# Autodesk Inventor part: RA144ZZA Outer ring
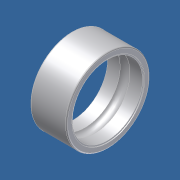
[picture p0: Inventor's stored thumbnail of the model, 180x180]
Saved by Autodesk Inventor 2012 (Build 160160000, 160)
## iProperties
Category: PARTsolutions
Created: 2011-07
Part Number: RA144ZZA Outer ring
Catalog Web Link: www.cadenas.de
Description: Six types or - Inch system sizes
Document SubType Name: Modeling
Designer: PARTsolutions
Density: 1 g/cm^3
Material: Par défaut
NB: RA144ZZA Outer ring
NN: Six types or
NT: Inch system sizes
NBSYN: RA144ZZA Outer ring
LINA: RA144ZZA Outer ring
SD: 3.175
D: 6.350
B: 2.380
B1: 2.779
D1: 7.52
D2: 7.52
C1: 0.58
C2: 0.79
R: 0.08
ORDER: RA144ZZA
CR: 284
COR: 96
CRF: 29
CORF: 10
LSG: 59000
LSO: 70000
MASS: 0.27
ORDER1: R144
WSS: RA144ZA
WDS: RA144ZZA
UTWF: FLR144
FORSS: FLRA144ZA
FORDS: FLRA144ZZA
DA1: 3.9
DA2: 4
DA: 5.5
RAS: 0.08
MASS1: 0.33
VERS: 3
X: 1.587
N: 9
O: 14.954
RB: 0.470
KT: DUMMY
SUPPLIER: NTN
ARTICLENO: RA144ZZA Outer ring
BOMINFO: RA144ZZA Outer ring
CREATOR: CADENAS GmbH
PSOL_IDENT_0: {\\10.0.0.251\ps_data\23d-libs\ntn\ball_roller_bearings\miniature_extra_small_bb\inch_system_sizes\i
PSOL_IDENT_1: ss_or.prj},189 {VTYP=3D},{NB=RA144ZZA Outer ring},{LINA=RA144ZZA Outer ring},{NN=Six types or},{DATE
PSOL_IDENT_2: =11.12.2007 08:48:22},{GEOMDATE=08.02.2007 08:30:00},{VERSION=},{LINEID=16080},{LINESUBID=-1},{WBVAR
PSOL_IDENT_3: =}  {NB=RA144ZZA Outer ring},{LINA=RA144ZZA Outer ring},{KT=DUMMY},{IDNR=},{SD=3.175},{D=6.350},{B=2
PSOL_IDENT_4: .380},{B1=2.779},{D1=7.52},{D2=7.52},{C1=0.58},{C2=0.79},{R=0.08},{ORDER=RA144ZZA},{CR=284},{COR=96}
PSOL_IDENT_5: ,{CRF=29},{CORF=10},{LSG=59000},{LSO=70000},{MASS=0.27},{ORDER1=R144},{WSS=RA144ZA},{WDS=RA144ZZA},{
PSOL_IDENT_6: UTWF=FLR144},{FORSS=FLRA144ZA},{FORDS=FLRA144ZZA},{DA1=3.9},{DA2=4},{DA=5.5},{RAS=0.08},{MASS1=0.33}
PSOL_IDENT_7: ,{VERS=3},{X=1.5875},{N=9},{O=14.95425},{RB=0.4699}
Title: RA144ZZA Outer ring
Author: Cadenas PARTsolutions
Comments: Inch system sizes
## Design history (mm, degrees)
sketch "Sketch_3"
  geometry: L1 (2.779, 0)-(0, 0); L2 (0, 3.095)-(0, 2.769); L3 (0, 2.769)-(0.063, 2.769); L4 (0.063, 2.769)-(0.063, 2.667); L5 (0.063, 2.667)-(1.016, 2.667); L6 (1.763, 2.667)-(2.716, 2.667); L7 (2.716, 2.667)-(2.716, 2.769); L8 (2.716, 2.769)-(2.779, 2.769); L9 (2.779, 2.769)-(2.779, 3.095); L10 (2.699, 3.175)-(0.08, 3.175); A1 r 0.47 centre (1.39, 2.381) between (1.763, 2.667) and (1.016, 2.667); A2 r 0.08 centre (2.699, 3.095) between (2.779, 3.095) and (2.699, 3.175); A3 r 0.08 centre (0.08, 3.095) between (0.08, 3.175) and (0, 3.095)
  constraints: 20 end point, 6 point on circle, 3 centre point
revolve "Revolution1" sketch "Sketch_3" stored, may be unused: angle "d0" = 360 deg
node "iss_or_XY"
node "iss_or_YZ"
node "iss_or_ZX"
node "iss_or_X"
node "iss_or_Y"
node "iss_or_Z"
node "iss_or_Center"
node "iss_or11_XY"
node "iss_or11_YZ"
node "iss_or11_ZX"
node "iss_or11_X"
node "iss_or11_Y"
node "iss_or11_Z"
node "iss_or11_Center"
node "iss_or2_9_XY"
node "iss_or2_9_YZ"
node "iss_or2_9_ZX"
node "iss_or2_9_X"
node "iss_or2_9_Y"
node "iss_or2_9_Z"
node "iss_or2_9_Center"
node "iss_or2_8_XY"
node "iss_or2_8_YZ"
node "iss_or2_8_ZX"
node "iss_or2_8_X"
node "iss_or2_8_Y"
node "iss_or2_8_Z"
node "iss_or2_8_Center"
node "iss_or2_1_XY"
node "iss_or2_1_YZ"
node "iss_or2_1_ZX"
node "iss_or2_1_X"
node "iss_or2_1_Y"
node "iss_or2_1_Z"
node "iss_or2_1_Center"
node "iss_or2_3_XY"
node "iss_or2_3_YZ"
node "iss_or2_3_ZX"
node "iss_or2_3_X"
node "iss_or2_3_Y"
node "iss_or2_3_Z"
node "iss_or2_3_Center"
node "iss_or2_2_XY"
node "iss_or2_2_YZ"
node "iss_or2_2_ZX"
node "iss_or2_2_X"
node "iss_or2_2_Y"
node "iss_or2_2_Z"
node "iss_or2_2_Center"
node "iss_or2_5_XY"
node "iss_or2_5_YZ"
node "iss_or2_5_ZX"
node "iss_or2_5_X"
node "iss_or2_5_Y"
node "iss_or2_5_Z"
node "iss_or2_5_Center"
node "iss_or2_4_XY"
node "iss_or2_4_YZ"
node "iss_or2_4_ZX"
node "iss_or2_4_X"
node "iss_or2_4_Y"
node "iss_or2_4_Z"
node "iss_or2_4_Center"
node "iss_or2_7_XY"
node "iss_or2_7_YZ"
node "iss_or2_7_ZX"
node "iss_or2_7_X"
node "iss_or2_7_Y"
node "iss_or2_7_Z"
node "iss_or2_7_Center"
node "iss_or2_6_XY"
node "iss_or2_6_YZ"
node "iss_or2_6_ZX"
node "iss_or2_6_X"
node "iss_or2_6_Y"
node "iss_or2_6_Z"
node "iss_or2_6_Center"
node "iss_or21_9_XY"
node "iss_or21_9_YZ"
node "iss_or21_9_ZX"
node "iss_or21_9_X"
node "iss_or21_9_Y"
node "iss_or21_9_Z"
node "iss_or21_9_Center"
node "iss_or21_8_XY"
node "iss_or21_8_YZ"
node "iss_or21_8_ZX"
node "iss_or21_8_X"
node "iss_or21_8_Y"
node "iss_or21_8_Z"
node "iss_or21_8_Center"
node "iss_or21_3_XY"
node "iss_or21_3_YZ"
node "iss_or21_3_ZX"
node "iss_or21_3_X"
node "iss_or21_3_Y"
node "iss_or21_3_Z"
node "iss_or21_3_Center"
node "iss_or21_2_XY"
node "iss_or21_2_YZ"
node "iss_or21_2_ZX"
node "iss_or21_2_X"
node "iss_or21_2_Y"
node "iss_or21_2_Z"
node "iss_or21_2_Center"
node "iss_or21_1_XY"
node "iss_or21_1_YZ"
node "iss_or21_1_ZX"
node "iss_or21_1_X"
node "iss_or21_1_Y"
node "iss_or21_1_Z"
node "iss_or21_1_Center"
node "iss_or21_7_XY"
node "iss_or21_7_YZ"
node "iss_or21_7_ZX"
node "iss_or21_7_X"
node "iss_or21_7_Y"
node "iss_or21_7_Z"
node "iss_or21_7_Center"
node "iss_or21_6_XY"
node "iss_or21_6_YZ"
node "iss_or21_6_ZX"
node "iss_or21_6_X"
node "iss_or21_6_Y"
node "iss_or21_6_Z"
node "iss_or21_6_Center"
node "iss_or21_5_XY"
node "iss_or21_5_YZ"
node "iss_or21_5_ZX"
node "iss_or21_5_X"
node "iss_or21_5_Y"
node "iss_or21_5_Z"
node "iss_or21_5_Center"
node "iss_or21_4_XY"
node "iss_or21_4_YZ"
node "iss_or21_4_ZX"
node "iss_or21_4_X"
node "iss_or21_4_Y"
node "iss_or21_4_Z"
node "iss_or21_4_Center"
node "Solide1"
node "Corps solides"
node "Corps surfaciques"
